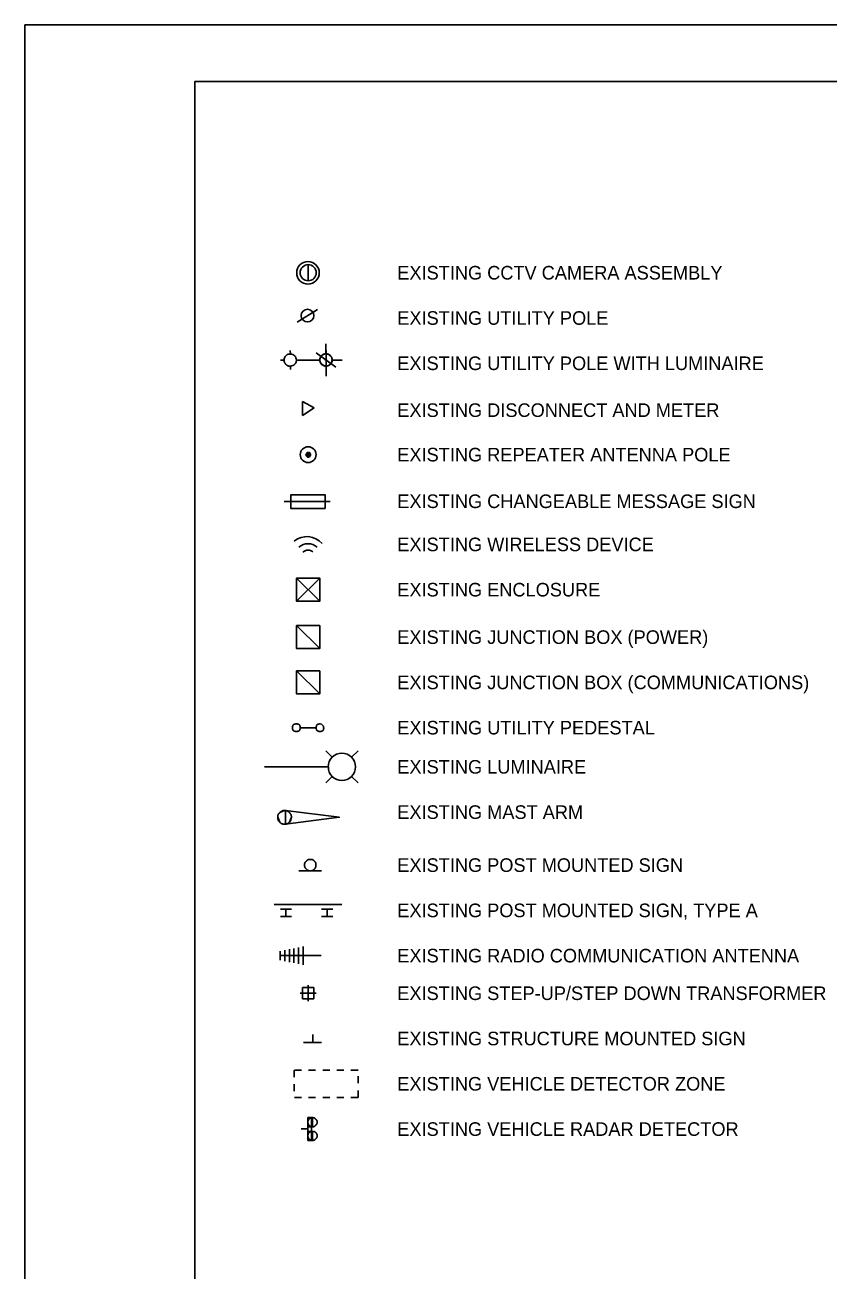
# Model space of a CAD drawing. Extents: x 1299104.8 to 1299141.6, y 239639.8 to 239661.8.
# Drawn here: x 1299104.8 to 1299111.89, y 239650.79 to 239661.79 of the extents above; entities that cross this region are included whole.
import ezdxf

# ---------------------------------------------------------------- set-up
doc = ezdxf.new("R2010")
doc.units = 0
for name, color, linetype in [('DIM TXT', 7, 'Continuous'), ('GS_noplot_1', 7, 'Continuous'), ('Level 1', 7, 'Continuous'), ('PDF2_Geometry', 7, 'Continuous'), ('PDF2_Solid Fills', 7, 'Continuous'), ('PDF3_Geometry', 7, 'Continuous'), ('PDF4_Geometry', 7, 'Continuous'), ('PDF_LEGEND', 7, 'Continuous')]:
    doc.layers.add(name, color=color, linetype=linetype)

msp = doc.modelspace()

# ---------------------------------------------------------------- linework, layer by layer
at = {"layer": 'GS_noplot_1'}
msp.add_lwpolyline([(1299104.802, 239661.791), (1299138.802, 239661.791), (1299138.802, 239639.791), (1299104.802, 239639.791)], close=True, dxfattribs=at)
at = {"layer": 'Level 1'}
msp.add_lwpolyline([(1299138.302, 239640.291), (1299106.302, 239640.291), (1299106.302, 239661.291), (1299138.302, 239661.291)], close=True, dxfattribs=at)
at = {"layer": 'PDF2_Geometry'}
for points in [[(1299107.515, 239655.322), (1299107.458, 239655.379)], [(1299107.685, 239655.322), (1299107.743, 239655.379)], [(1299107.48, 239655.237), (1299106.917, 239655.237)], [(1299107.458, 239655.095), (1299107.515, 239655.152)], [(1299107.743, 239655.095), (1299107.685, 239655.152)], [(1299107.221, 239654.319), (1299107.422, 239654.319)], [(1299107.057, 239653.61), (1299107.057, 239653.529)], [(1299107.098, 239653.617), (1299107.098, 239653.52)], [(1299107.138, 239653.625), (1299107.138, 239653.512)], [(1299107.177, 239653.633), (1299107.177, 239653.505)], [(1299107.218, 239653.642), (1299107.218, 239653.497)], [(1299107.258, 239653.649), (1299107.258, 239653.488)], [(1299107.419, 239653.569), (1299107.057, 239653.569)], [(1299107.343, 239652.872), (1299107.343, 239652.802)], [(1299107.422, 239652.802), (1299107.262, 239652.802)], [(1299107.18, 239652.558), (1299107.18, 239652.495)], [(1299107.245, 239652.558), (1299107.183, 239652.558)], [(1299107.369, 239652.558), (1299107.307, 239652.558)], [(1299107.494, 239652.558), (1299107.432, 239652.558)], [(1299107.618, 239652.558), (1299107.556, 239652.558)], [(1299107.743, 239652.558), (1299107.681, 239652.558)], [(1299107.743, 239652.442), (1299107.743, 239652.503)], [(1299107.18, 239652.434), (1299107.18, 239652.371)], [(1299107.245, 239652.316), (1299107.183, 239652.316)], [(1299107.369, 239652.316), (1299107.307, 239652.316)], [(1299107.494, 239652.316), (1299107.432, 239652.316)], [(1299107.618, 239652.316), (1299107.556, 239652.316)], [(1299107.743, 239652.379), (1299107.743, 239652.316), (1299107.681, 239652.316)], [(1299107.301, 239652.138), (1299107.332, 239652.138)], [(1299107.301, 239652.038), (1299107.241, 239652.038)]]:
    msp.add_lwpolyline(points, dxfattribs=at)
for centre, start, end in [((1299107.6, 239655.237), 89.9963, 180.0037), ((1299107.6, 239655.237), 359.9963, 90.0037), ((1299107.601, 239655.236), 179.4773, 269.8603), ((1299107.6, 239655.236), 270.1397, 0.5227)]:
    msp.add_arc(centre, 0.12, start, end, dxfattribs=at)
for points in [[(1299107.052, 239654.833), (1299107.041, 239654.822), (1299107.034, 239654.806), (1299107.034, 239654.791)], [(1299107.137, 239654.833), (1299107.126, 239654.844), (1299107.11, 239654.851), (1299107.095, 239654.851)], [(1299107.155, 239654.791), (1299107.155, 239654.806), (1299107.148, 239654.822), (1299107.137, 239654.833)], [(1299107.052, 239654.748), (1299107.063, 239654.737), (1299107.078, 239654.731), (1299107.095, 239654.731)], [(1299107.095, 239654.731), (1299107.11, 239654.731), (1299107.126, 239654.737), (1299107.137, 239654.748)], [(1299107.287, 239654.405), (1299107.277, 239654.396), (1299107.271, 239654.383), (1299107.271, 239654.369)], [(1299107.271, 239654.369), (1299107.271, 239654.356), (1299107.277, 239654.343), (1299107.287, 239654.334)], [(1299107.322, 239654.419), (1299107.309, 239654.419), (1299107.296, 239654.414), (1299107.287, 239654.405)], [(1299107.358, 239654.405), (1299107.348, 239654.414), (1299107.336, 239654.419), (1299107.322, 239654.419)], [(1299107.372, 239654.369), (1299107.372, 239654.383), (1299107.366, 239654.396), (1299107.358, 239654.405)], [(1299107.358, 239654.334), (1299107.366, 239654.343), (1299107.372, 239654.356), (1299107.372, 239654.369)], [(1299107.287, 239654.334), (1299107.296, 239654.324), (1299107.309, 239654.319), (1299107.322, 239654.319)], [(1299107.322, 239654.319), (1299107.336, 239654.319), (1299107.348, 239654.324), (1299107.358, 239654.334)], [(1299107.312, 239652.126), (1299107.305, 239652.119), (1299107.301, 239652.109), (1299107.301, 239652.098)], [(1299107.301, 239652.098), (1299107.301, 239652.087), (1299107.305, 239652.077), (1299107.312, 239652.07)], [(1299107.341, 239652.138), (1299107.33, 239652.138), (1299107.32, 239652.134), (1299107.312, 239652.126)], [(1299107.312, 239652.07), (1299107.32, 239652.062), (1299107.33, 239652.057), (1299107.341, 239652.057)], [(1299107.369, 239652.126), (1299107.362, 239652.134), (1299107.351, 239652.138), (1299107.341, 239652.138)], [(1299107.341, 239652.057), (1299107.351, 239652.057), (1299107.362, 239652.062), (1299107.369, 239652.07)], [(1299107.382, 239652.098), (1299107.382, 239652.109), (1299107.376, 239652.119), (1299107.369, 239652.126)], [(1299107.369, 239652.07), (1299107.376, 239652.077), (1299107.382, 239652.087), (1299107.382, 239652.098)], [(1299107.312, 239652.006), (1299107.305, 239651.999), (1299107.301, 239651.988), (1299107.301, 239651.978)], [(1299107.301, 239651.978), (1299107.301, 239651.967), (1299107.305, 239651.957), (1299107.312, 239651.949)], [(1299107.341, 239652.017), (1299107.33, 239652.017), (1299107.32, 239652.013), (1299107.312, 239652.006)], [(1299107.312, 239651.949), (1299107.32, 239651.942), (1299107.33, 239651.937), (1299107.341, 239651.937)], [(1299107.369, 239652.006), (1299107.362, 239652.013), (1299107.351, 239652.017), (1299107.341, 239652.017)], [(1299107.341, 239651.937), (1299107.351, 239651.937), (1299107.362, 239651.942), (1299107.369, 239651.949)], [(1299107.382, 239651.978), (1299107.382, 239651.988), (1299107.376, 239651.999), (1299107.369, 239652.006)], [(1299107.369, 239651.949), (1299107.376, 239651.957), (1299107.382, 239651.967), (1299107.382, 239651.978)]]:
    msp.add_open_spline(points, degree=2, dxfattribs=at)
at = {"layer": 'PDF2_Solid Fills'}
for p, q in [((1299107.052, 239654.833), (1299107.095, 239654.851)), ((1299107.052, 239654.748), (1299107.034, 239654.791)), ((1299107.155, 239654.791), (1299107.137, 239654.748))]:
    msp.add_line(p, q, dxfattribs=at)
for points in [[(1299107.102, 239654.731), (1299107.577, 239654.791), (1299107.102, 239654.851)], [(1299107.301, 239651.937), (1299107.332, 239651.937), (1299107.332, 239652.138), (1299107.301, 239652.138)], [(1299107.341, 239652.057), (1299107.301, 239652.057), (1299107.301, 239652.138), (1299107.341, 239652.138)], [(1299107.341, 239652.017), (1299107.301, 239652.017), (1299107.301, 239651.937), (1299107.341, 239651.937)]]:
    msp.add_lwpolyline(points, close=True, dxfattribs=at)
for centre, start, end in [((1299107.095, 239654.79), 90.2249, 135.277), ((1299107.095, 239654.791), 180.2249, 225.277), ((1299107.094, 239654.791), 314.723, 359.7751)]:
    msp.add_arc(centre, 0.0612, start, end, dxfattribs=at)
at = {"layer": 'PDF3_Geometry'}
for points in [[(1299107.146, 239658.884), (1299107.144, 239658.915)], [(1299107.547, 239658.768), (1299107.373, 239658.894)], [(1299107.46, 239658.893), (1299107.46, 239658.975)], [(1299107.461, 239658.748), (1299107.461, 239658.916)], [(1299107.091, 239658.831), (1299107.06, 239658.831)], [(1299107.146, 239658.746), (1299107.146, 239658.777)], [(1299107.407, 239658.831), (1299107.199, 239658.831)], [(1299107.398, 239658.831), (1299107.316, 239658.831)], [(1299107.461, 239658.77), (1299107.461, 239658.688)], [(1299107.522, 239658.831), (1299107.603, 239658.831)], [(1299107.302, 239653.167), (1299107.302, 239653.308)], [(1299107.373, 239653.238), (1299107.232, 239653.238)]]:
    msp.add_lwpolyline(points, dxfattribs=at)
msp.add_lwpolyline([(1299107.253, 239653.188), (1299107.352, 239653.188), (1299107.352, 239653.287), (1299107.253, 239653.287)], close=True, dxfattribs=at)
for centre, radius, start, end in [((1299107.146, 239658.83), 0.0539, 45.6676, 89.9997), ((1299107.461, 239658.836), 0.0498, 89.5273, 138.3977), ((1299107.461, 239658.836), 0.0498, 41.6023, 90.4727), ((1299107.145, 239658.831), 0.0539, 135.6676, 179.9997), ((1299107.146, 239658.831), 0.0539, 270.0003, 314.3324), ((1299107.145, 239658.831), 0.0539, 0.0003, 44.3324), ((1299107.456, 239658.832), 0.0498, 131.6023, 180.4727), ((1299107.464, 239658.835), 0.0587, 191.9693, 233.2692), ((1299107.461, 239658.832), 0.0539, 225.6676, 314.3324)]:
    msp.add_arc(centre, radius, start, end, dxfattribs=at)
for points in [[(1299107.146, 239658.884), (1299107.13, 239658.884), (1299107.116, 239658.879), (1299107.107, 239658.869)], [(1299107.433, 239658.877), (1299107.42, 239658.87), (1299107.412, 239658.859), (1299107.408, 239658.845)], [(1299107.451, 239658.884), (1299107.437, 239658.883), (1299107.425, 239658.874), (1299107.416, 239658.863)], [(1299107.473, 239658.883), (1299107.46, 239658.887), (1299107.446, 239658.884), (1299107.433, 239658.877)], [(1299107.492, 239658.874), (1299107.48, 239658.883), (1299107.465, 239658.887), (1299107.451, 239658.884)], [(1299107.507, 239658.858), (1299107.499, 239658.87), (1299107.487, 239658.88), (1299107.473, 239658.883)], [(1299107.513, 239658.84), (1299107.511, 239658.854), (1299107.503, 239658.866), (1299107.492, 239658.874)], [(1299107.091, 239658.831), (1299107.091, 239658.816), (1299107.097, 239658.803), (1299107.107, 239658.792)], [(1299107.107, 239658.792), (1299107.118, 239658.782), (1299107.13, 239658.777), (1299107.146, 239658.777)], [(1299107.183, 239658.792), (1299107.193, 239658.803), (1299107.199, 239658.817), (1299107.199, 239658.831)], [(1299107.416, 239658.863), (1299107.408, 239658.851), (1299107.405, 239658.837), (1299107.407, 239658.823)], [(1299107.408, 239658.845), (1299107.405, 239658.831), (1299107.407, 239658.817), (1299107.413, 239658.805)], [(1299107.407, 239658.831), (1299107.407, 239658.817), (1299107.413, 239658.803), (1299107.423, 239658.794)], [(1299107.413, 239658.805), (1299107.42, 239658.792), (1299107.433, 239658.784), (1299107.447, 239658.78)], [(1299107.429, 239658.788), (1299107.44, 239658.78), (1299107.454, 239658.775), (1299107.469, 239658.778)], [(1299107.447, 239658.78), (1299107.46, 239658.777), (1299107.475, 239658.778), (1299107.487, 239658.785)], [(1299107.46, 239658.835), (1299107.458, 239658.835), (1299107.455, 239658.834), (1299107.455, 239658.831)], [(1299107.455, 239658.831), (1299107.455, 239658.828), (1299107.458, 239658.827), (1299107.46, 239658.827)], [(1299107.464, 239658.831), (1299107.464, 239658.834), (1299107.462, 239658.835), (1299107.46, 239658.835)], [(1299107.46, 239658.827), (1299107.462, 239658.827), (1299107.464, 239658.828), (1299107.464, 239658.831)], [(1299107.469, 239658.778), (1299107.483, 239658.781), (1299107.496, 239658.788), (1299107.504, 239658.801)], [(1299107.487, 239658.785), (1299107.499, 239658.792), (1299107.508, 239658.805), (1299107.511, 239658.817)], [(1299107.515, 239658.831), (1299107.514, 239658.845), (1299107.508, 239658.859), (1299107.499, 239658.869)], [(1299107.499, 239658.794), (1299107.508, 239658.803), (1299107.515, 239658.817), (1299107.515, 239658.831)], [(1299107.504, 239658.801), (1299107.513, 239658.812), (1299107.515, 239658.826), (1299107.513, 239658.84)], [(1299107.511, 239658.817), (1299107.515, 239658.831), (1299107.514, 239658.847), (1299107.507, 239658.858)]]:
    msp.add_open_spline(points, degree=2, dxfattribs=at)
at = {"layer": 'PDF4_Geometry'}
msp.add_lwpolyline([(1299107.232, 239655.583), (1299107.374, 239655.583)], dxfattribs=at)
msp.add_arc((1299107.408, 239655.584), 0.0316, 359.0546, 90.9454, dxfattribs=at)
for points in [[(1299107.199, 239655.616), (1299107.18, 239655.616), (1299107.165, 239655.602), (1299107.165, 239655.583)], [(1299107.165, 239655.583), (1299107.165, 239655.564), (1299107.18, 239655.55), (1299107.199, 239655.55)], [(1299107.232, 239655.583), (1299107.232, 239655.602), (1299107.217, 239655.616), (1299107.199, 239655.616)], [(1299107.199, 239655.55), (1299107.217, 239655.55), (1299107.232, 239655.564), (1299107.232, 239655.583)], [(1299107.408, 239655.616), (1299107.39, 239655.616), (1299107.374, 239655.602), (1299107.374, 239655.583)], [(1299107.374, 239655.583), (1299107.374, 239655.564), (1299107.39, 239655.55), (1299107.408, 239655.55)], [(1299107.408, 239655.55), (1299107.426, 239655.55), (1299107.44, 239655.564), (1299107.44, 239655.583)]]:
    msp.add_open_spline(points, degree=2, dxfattribs=at)
at = {"layer": 'PDF_LEGEND'}
for p, q in [((1299107.206, 239659.166), (1299107.386, 239659.278)), ((1299107.252, 239658.464), (1299107.355, 239658.407)), ((1299107.252, 239658.34), (1299107.252, 239658.464)), ((1299107.355, 239658.407), (1299107.252, 239658.34)), ((1299107.004, 239654.021), (1299107.601, 239654.021)), ((1299107.058, 239653.981), (1299107.156, 239653.981)), ((1299107.107, 239653.981), (1299107.107, 239653.914)), ((1299107.422, 239653.981), (1299107.52, 239653.981)), ((1299107.471, 239653.981), (1299107.471, 239653.914)), ((1299107.058, 239653.914), (1299107.156, 239653.914)), ((1299107.422, 239653.914), (1299107.52, 239653.914))]:
    msp.add_line(p, q, dxfattribs=at)
for points in [[(1299107.302, 239659.532), (1299107.302, 239659.673)], [(1299107.09, 239657.58), (1299107.497, 239657.58)], [(1299107.405, 239656.904), (1299107.2, 239656.7)], [(1299107.2, 239656.904), (1299107.405, 239656.7)]]:
    msp.add_lwpolyline(points, dxfattribs=at)
for points in [[(1299107.285, 239657.998), (1299107.323, 239657.995), (1299107.283, 239657.995)], [(1299107.323, 239657.995), (1299107.283, 239657.995), (1299107.323, 239657.991)], [(1299107.283, 239657.995), (1299107.323, 239657.991), (1299107.285, 239657.991)], [(1299107.287, 239658.005), (1299107.323, 239658.001), (1299107.285, 239658.001)], [(1299107.323, 239658.001), (1299107.285, 239658.001), (1299107.323, 239657.998)], [(1299107.285, 239658.001), (1299107.323, 239657.998), (1299107.285, 239657.998)], [(1299107.323, 239657.998), (1299107.285, 239657.998), (1299107.323, 239657.995)], [(1299107.323, 239657.991), (1299107.285, 239657.991), (1299107.323, 239657.986)], [(1299107.285, 239657.991), (1299107.323, 239657.986), (1299107.285, 239657.986)], [(1299107.29, 239658.008), (1299107.322, 239658.005), (1299107.287, 239658.005)], [(1299107.322, 239658.005), (1299107.287, 239658.005), (1299107.323, 239658.001)], [(1299107.292, 239658.01), (1299107.318, 239658.008), (1299107.29, 239658.008)], [(1299107.318, 239658.008), (1299107.29, 239658.008), (1299107.322, 239658.005)], [(1299107.295, 239658.013), (1299107.317, 239658.01), (1299107.292, 239658.01)], [(1299107.317, 239658.01), (1299107.292, 239658.01), (1299107.318, 239658.008)], [(1299107.298, 239658.013), (1299107.313, 239658.013), (1299107.295, 239658.013)], [(1299107.313, 239658.013), (1299107.295, 239658.013), (1299107.317, 239658.01)], [(1299107.302, 239658.015), (1299107.31, 239658.013), (1299107.298, 239658.013)], [(1299107.31, 239658.013), (1299107.298, 239658.013), (1299107.313, 239658.013)], [(1299107.305, 239658.015), (1299107.302, 239658.015), (1299107.31, 239658.013)], [(1299107.323, 239657.986), (1299107.285, 239657.986), (1299107.322, 239657.983)], [(1299107.285, 239657.986), (1299107.322, 239657.983), (1299107.287, 239657.983)], [(1299107.322, 239657.983), (1299107.287, 239657.983), (1299107.318, 239657.981)], [(1299107.287, 239657.983), (1299107.318, 239657.981), (1299107.29, 239657.981)], [(1299107.318, 239657.981), (1299107.29, 239657.981), (1299107.317, 239657.978)], [(1299107.29, 239657.981), (1299107.317, 239657.978), (1299107.292, 239657.978)], [(1299107.317, 239657.978), (1299107.292, 239657.978), (1299107.313, 239657.976)], [(1299107.292, 239657.978), (1299107.313, 239657.976), (1299107.295, 239657.976)], [(1299107.313, 239657.976), (1299107.295, 239657.976), (1299107.31, 239657.974)], [(1299107.295, 239657.976), (1299107.31, 239657.974), (1299107.298, 239657.974)], [(1299107.31, 239657.974), (1299107.298, 239657.974), (1299107.305, 239657.974)], [(1299107.298, 239657.974), (1299107.305, 239657.974), (1299107.302, 239657.974)], [(1299107.452, 239657.519), (1299107.151, 239657.519), (1299107.151, 239657.64), (1299107.452, 239657.64)], [(1299107.324, 239656.904), (1299107.405, 239656.904), (1299107.405, 239656.78), (1299107.405, 239656.7), (1299107.326, 239656.7), (1299107.2, 239656.7), (1299107.2, 239656.824), (1299107.2, 239656.904)], [(1299107.2, 239656.485), (1299107.405, 239656.485), (1299107.405, 239656.485)], [(1299107.405, 239656.281), (1299107.2, 239656.281), (1299107.2, 239656.485)], [(1299107.2, 239656.485), (1299107.405, 239656.485), (1299107.405, 239656.281)], [(1299107.405, 239656.281), (1299107.405, 239656.281), (1299107.2, 239656.281)], [(1299107.405, 239656.085), (1299107.405, 239655.881), (1299107.2, 239655.881), (1299107.2, 239656.085)], [(1299107.405, 239655.881), (1299107.2, 239656.085), (1299107.405, 239656.085)]]:
    msp.add_lwpolyline(points, close=True, dxfattribs=at)
for centre, radius in [((1299107.301, 239659.602), 0.0996), ((1299107.303, 239659.602), 0.0712), ((1299107.297, 239659.223), 0.0561), ((1299107.303, 239657.995), 0.0695), ((1299107.304, 239657.995), 0.0193)]:
    msp.add_circle(centre, radius, dxfattribs=at)
for centre, radius, start, end in [((1299107.292, 239657.091), 0.18, 41.2482, 129.2102), ((1299107.302, 239657.088), 0.12, 48.0048, 132.616), ((1299107.302, 239657.091), 0.0611, 46.2799, 137.818)]:
    msp.add_arc(centre, radius, start, end, dxfattribs=at)

# ---------------------------------------------------------------- texts
at = {"layer": 'DIM TXT'}
for s, p in [('EXISTING CCTV CAMERA ASSEMBLY', (1299108.09, 239659.542)), ('EXISTING UTILITY POLE', (1299108.09, 239659.142)), ('EXISTING UTILITY POLE WITH LUMINAIRE', (1299108.09, 239658.742)), ('EXISTING DISCONNECT AND METER', (1299108.09, 239658.328)), ('EXISTING REPEATER ANTENNA POLE', (1299108.09, 239657.935)), ('EXISTING CHANGEABLE MESSAGE SIGN', (1299108.09, 239657.523)), ('EXISTING WIRELESS DEVICE', (1299108.09, 239657.142)), ('EXISTING ENCLOSURE', (1299108.09, 239656.742)), ('EXISTING JUNCTION BOX (POWER)', (1299108.09, 239656.323)), ('EXISTING JUNCTION BOX (COMMUNICATIONS)', (1299108.09, 239655.923)), ('EXISTING UTILITY PEDESTAL', (1299108.09, 239655.523)), ('EXISTING LUMINAIRE', (1299108.09, 239655.177)), ('EXISTING MAST ARM', (1299108.09, 239654.777)), ('EXISTING POST MOUNTED SIGN', (1299108.09, 239654.309)), ('EXISTING POST MOUNTED SIGN, TYPE A', (1299108.09, 239653.909)), ('EXISTING RADIO COMMUNICATION ANTENNA', (1299108.09, 239653.509)), ('EXISTING STEP-UP/STEP DOWN TRANSFORMER', (1299108.09, 239653.177)), ('EXISTING STRUCTURE MOUNTED SIGN', (1299108.09, 239652.777)), ('EXISTING VEHICLE DETECTOR ZONE', (1299108.09, 239652.377)), ('EXISTING VEHICLE RADAR DETECTOR', (1299108.09, 239651.977))]:
    msp.add_text(s, height=0.12, dxfattribs=at).set_placement(p)

doc.saveas('drawing.dxf')
